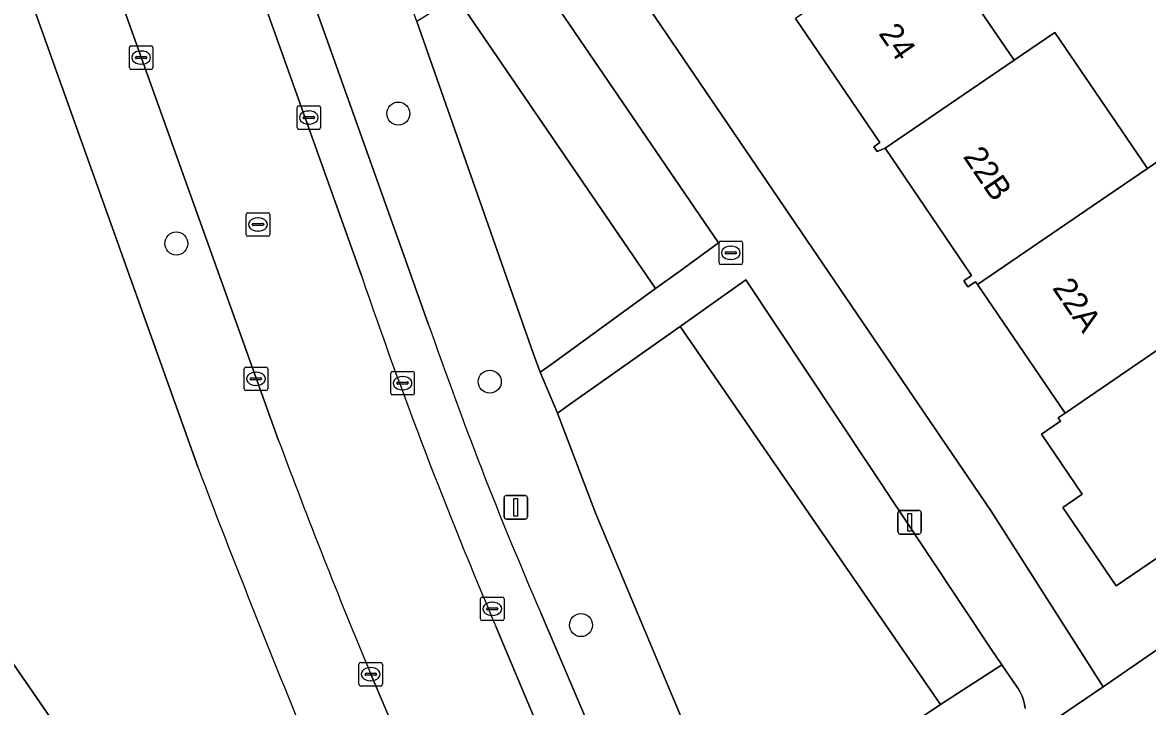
# Model space of a CAD drawing. Extents: x 157445 to 158888, y 383061 to 384688.
# Drawn here: x 158006.18 to 158053.95, y 383391.87 to 383420.9 of the extents above; entities that cross this region are included whole.
import ezdxf

# ---------------------------------------------------------------- set-up
doc = ezdxf.new("R2010")
doc.units = 0
for name, color, linetype in [('IMGEO_Boom', 7, 'Continuous'), ('IMGEO_Erf', 7, 'Continuous'), ('IMGEO_Groenvoorziening', 7, 'Continuous'), ('IMGEO_Kolk', 7, 'Continuous'), ('IMGEO_Lichtmast', 7, 'Continuous'), ('IMGEO_Pand', 7, 'Continuous'), ('IMGEO_Pand_nummerreeks', 7, 'Continuous'), ('IMGEO_Parkeervlak_open', 7, 'Continuous'), ('IMGEO_Rijbaan_lokaal_gesloten', 7, 'Continuous'), ('IMGEO_Rioolput', 7, 'Continuous'), ('IMGEO_Voetpad_open', 7, 'Continuous')]:
    doc.layers.add(name, color=color, linetype=linetype)

msp = doc.modelspace()

# ---------------------------------------------------------------- linework, layer by layer
at = {"layer": 'IMGEO_Boom'}
for centre in [(158022.135, 383417.035), (158012.708, 383411.521), (158026.019, 383405.658), (158029.891, 383395.328)]:
    msp.add_circle(centre, 0.489, dxfattribs=at)
at = {"layer": 'IMGEO_Erf'}
for points in [[(158056.615, 383429.6), (158053.223, 383434.593), (158051.051, 383433.111), (158049.016, 383436.093), (158046.866, 383439.244), (158049.038, 383440.726), (158045.945, 383445.259), (158044.482, 383444.292), (158039.206, 383440.804), (158028.037, 383433.42), (158028.2, 383433.181), (158025.942, 383431.583), (158047.304, 383400.16), (158052.068, 383392.71), (158058.3, 383397.002)], [(158013.62, 383402.046), (158004.962, 383426.227), (158004.459, 383427.633), (158000.558, 383426.024)], [(158044.512, 383424.838), (158048.284, 383419.3), (158050.011, 383420.476), (158053.943, 383414.702), (158055.521, 383415.778)], [(158056.504, 383399.639), (158052.618, 383396.993), (158050.349, 383400.324), (158051.176, 383400.887), (158049.442, 383403.432), (158050.252, 383403.984), (158050.154, 383404.128), (158050.445, 383404.327), (158046.73, 383409.781), (158046.649, 383409.9), (158046.322, 383409.677), (158046.142, 383409.941), (158046.477, 383410.169), (158042.804, 383415.561), (158042.471, 383415.422), (158042.33, 383415.629), (158042.586, 383415.803), (158038.995, 383421.074)]]:
    msp.add_lwpolyline(points, dxfattribs=at)
msp.add_lwpolyline([(157981.4, 383406.529), (157984.101, 383408.396), (157991.898, 383413.783), (158000, 383402.05), (158014.654, 383380.83), (158014.224, 383380.534), (158006.84, 383375.45), (158002.435, 383372.417), (158000, 383375.946), (157993.757, 383384.994), (157990.787, 383389.287), (157990.398, 383389.849), (157983.821, 383399.385), (157981.515, 383402.715), (157983.246, 383403.901)], close=True, dxfattribs=at)
msp.add_arc((158391.121, 383545.013), 403.666, 200.74263, 202.81798, dxfattribs=at)
at = {"layer": 'IMGEO_Groenvoorziening'}
for points in [[(158027.4, 383423.773), (158024.62, 383421.967), (158033.06, 383409.607), (158034.083, 383410.348), (158035.735, 383411.543)], [(158022.919, 383420.946), (158027.86, 383406.874), (158028.157, 383406.056), (158028.619, 383406.39), (158033.06, 383409.607), (158024.62, 383421.967), (158023.399, 383421.234)], [(158036.898, 383409.977), (158034.101, 383407.999), (158045.156, 383391.955), (158047.758, 383393.647), (158047.302, 383394.311)], [(158034.101, 383407.999), (158029.41, 383404.684), (158028.89, 383404.32), (158030.52, 383400.045), (158034.143, 383391.42), (158035.809, 383387.677), (158036.432, 383386.518), (158036.596, 383386.232), (158045.156, 383391.955)]]:
    msp.add_lwpolyline(points, close=True, dxfattribs=at)
msp.add_lwpolyline([(158048.757, 383391.791), (158048.727, 383391.969), (158048.681, 383392.145), (158048.619, 383392.316), (158048.542, 383392.48), (158048.451, 383392.637), (158048.417, 383392.688), (158047.758, 383393.647), (158045.156, 383391.955), (158036.596, 383386.232), (158036.774, 383385.921), (158037.176, 383385.22)], dxfattribs=at)
at = {"layer": 'IMGEO_Kolk'}
for p, q in [((158010.715, 383418.984), (158010.715, 383419.836)), ((158010.79, 383419.91), (158011.642, 383419.91)), ((158011.203, 383419.69), (158011.228, 383419.69)), ((158011.716, 383419.836), (158011.716, 383418.984)), ((158010.974, 383419.404), (158010.974, 383419.416)), ((158011.412, 383419.367), (158011.014, 383419.367)), ((158011.017, 383419.453), (158011.415, 383419.453)), ((158011.226, 383419.13), (158011.201, 383419.13)), ((158011.458, 383419.416), (158011.458, 383419.404)), ((158011.642, 383418.91), (158010.79, 383418.91)), ((158017.835, 383416.439), (158017.835, 383417.291)), ((158017.91, 383417.365), (158018.762, 383417.365)), ((158018.323, 383417.145), (158018.348, 383417.145)), ((158018.836, 383417.291), (158018.836, 383416.439)), ((158018.094, 383416.859), (158018.094, 383416.871)), ((158018.532, 383416.822), (158018.134, 383416.822)), ((158018.137, 383416.908), (158018.535, 383416.908)), ((158018.578, 383416.871), (158018.578, 383416.859)), ((158018.762, 383416.365), (158017.91, 383416.365)), ((158018.346, 383416.585), (158018.321, 383416.585)), ((158035.754, 383410.698), (158035.754, 383411.55)), ((158035.829, 383411.624), (158036.681, 383411.624)), ((158036.242, 383411.404), (158036.267, 383411.404)), ((158036.755, 383411.55), (158036.755, 383410.698)), ((158036.013, 383411.118), (158036.013, 383411.13)), ((158036.451, 383411.081), (158036.053, 383411.081)), ((158036.056, 383411.167), (158036.454, 383411.167)), ((158036.497, 383411.13), (158036.497, 383411.118)), ((158036.681, 383410.624), (158035.829, 383410.624)), ((158036.265, 383410.844), (158036.24, 383410.844)), ((158015.589, 383405.351), (158015.589, 383406.203)), ((158015.664, 383406.277), (158016.516, 383406.277)), ((158016.59, 383406.203), (158016.59, 383405.351)), ((158015.848, 383405.771), (158015.848, 383405.783)), ((158016.286, 383405.734), (158015.888, 383405.734)), ((158015.891, 383405.82), (158016.289, 383405.82)), ((158016.077, 383406.057), (158016.102, 383406.057)), ((158016.332, 383405.783), (158016.332, 383405.771)), ((158021.814, 383405.17), (158021.814, 383406.022)), ((158021.889, 383406.096), (158022.741, 383406.096)), ((158022.302, 383405.876), (158022.327, 383405.876)), ((158022.815, 383406.022), (158022.815, 383405.17)), ((158016.516, 383405.277), (158015.664, 383405.277)), ((158016.1, 383405.497), (158016.075, 383405.497)), ((158022.073, 383405.59), (158022.073, 383405.602)), ((158022.511, 383405.553), (158022.113, 383405.553)), ((158022.116, 383405.639), (158022.514, 383405.639)), ((158022.325, 383405.316), (158022.3, 383405.316)), ((158022.557, 383405.602), (158022.557, 383405.59)), ((158022.741, 383405.096), (158021.889, 383405.096)), ((158025.623, 383395.59), (158025.623, 383396.442)), ((158025.698, 383396.516), (158026.55, 383396.516)), ((158026.111, 383396.296), (158026.136, 383396.296)), ((158026.624, 383396.442), (158026.624, 383395.59)), ((158025.882, 383396.01), (158025.882, 383396.022)), ((158026.32, 383395.973), (158025.922, 383395.973)), ((158025.925, 383396.059), (158026.323, 383396.059)), ((158026.134, 383395.736), (158026.109, 383395.736)), ((158026.366, 383396.022), (158026.366, 383396.01)), ((158026.55, 383395.516), (158025.698, 383395.516)), ((158020.538, 383393.741), (158021.39, 383393.741)), ((158020.463, 383392.815), (158020.463, 383393.667)), ((158020.722, 383393.235), (158020.722, 383393.247)), ((158020.765, 383393.284), (158021.163, 383393.284)), ((158020.951, 383393.521), (158020.976, 383393.521)), ((158021.206, 383393.247), (158021.206, 383393.235)), ((158021.464, 383393.667), (158021.464, 383392.815)), ((158021.16, 383393.198), (158020.762, 383393.198)), ((158020.974, 383392.961), (158020.949, 383392.961)), ((158021.39, 383392.741), (158020.538, 383392.741))]:
    msp.add_line(p, q, dxfattribs=at)
for points in [[(158010.715, 383418.984), (158010.715, 383419.836)], [(158010.79, 383419.91), (158011.642, 383419.91)], [(158011.716, 383419.836), (158011.716, 383418.984)], [(158011.642, 383418.91), (158010.79, 383418.91)], [(158017.835, 383416.439), (158017.835, 383417.291)], [(158017.91, 383417.365), (158018.762, 383417.365)], [(158018.836, 383417.291), (158018.836, 383416.439)], [(158018.762, 383416.365), (158017.91, 383416.365)], [(158035.754, 383410.698), (158035.754, 383411.55)], [(158035.829, 383411.624), (158036.681, 383411.624)], [(158036.755, 383411.55), (158036.755, 383410.698)], [(158036.681, 383410.624), (158035.829, 383410.624)], [(158015.589, 383405.351), (158015.589, 383406.203)], [(158015.664, 383406.277), (158016.516, 383406.277)], [(158016.59, 383406.203), (158016.59, 383405.351)], [(158021.814, 383405.17), (158021.814, 383406.022)], [(158021.889, 383406.096), (158022.741, 383406.096)], [(158022.815, 383406.022), (158022.815, 383405.17)], [(158016.516, 383405.277), (158015.664, 383405.277)], [(158022.741, 383405.096), (158021.889, 383405.096)], [(158025.623, 383395.59), (158025.623, 383396.442)], [(158025.698, 383396.516), (158026.55, 383396.516)], [(158026.624, 383396.442), (158026.624, 383395.59)], [(158026.55, 383395.516), (158025.698, 383395.516)], [(158020.538, 383393.741), (158021.39, 383393.741)], [(158020.463, 383392.815), (158020.463, 383393.667)], [(158021.464, 383393.667), (158021.464, 383392.815)], [(158021.39, 383392.741), (158020.538, 383392.741)]]:
    msp.add_lwpolyline(points, dxfattribs=at)
for centre, radius, start, end in [((158010.792, 383419.834), 0.0765, 91.552, 178.448), ((158010.792, 383419.834), 0.0765, 91.552, 178.448), ((158011.64, 383419.834), 0.0765, 1.552, 88.448), ((158011.64, 383419.834), 0.0765, 1.552, 88.448), ((158011.014, 383419.413), 0.0403, 85.8775, 175.7526), ((158011.011, 383419.403), 0.0366, 178.938, 274.7102), ((158011.415, 383419.41), 0.043, 264.8664, 352.4533), ((158011.419, 383419.415), 0.0386, 1.7309, 96.639), ((158010.792, 383418.986), 0.0765, 181.552, 268.448), ((158010.792, 383418.986), 0.0765, 181.552, 268.448), ((158011.64, 383418.986), 0.0765, 271.552, 358.448), ((158011.64, 383418.986), 0.0765, 271.552, 358.448), ((158017.912, 383417.289), 0.0765, 91.552, 178.448), ((158017.912, 383417.289), 0.0765, 91.552, 178.448), ((158018.76, 383417.289), 0.0765, 1.552, 88.448), ((158018.76, 383417.289), 0.0765, 1.552, 88.448), ((158018.134, 383416.868), 0.0403, 85.8775, 175.7526), ((158018.131, 383416.858), 0.0366, 178.938, 274.7102), ((158018.535, 383416.865), 0.043, 264.8664, 352.4533), ((158018.539, 383416.87), 0.0386, 1.7309, 96.639), ((158017.912, 383416.441), 0.0765, 181.552, 268.448), ((158017.912, 383416.441), 0.0765, 181.552, 268.448), ((158018.76, 383416.441), 0.0765, 271.552, 358.448), ((158018.76, 383416.441), 0.0765, 271.552, 358.448), ((158035.831, 383411.548), 0.0765, 91.552, 178.448), ((158035.831, 383411.548), 0.0765, 91.552, 178.448), ((158036.679, 383411.548), 0.0765, 1.552, 88.448), ((158036.679, 383411.548), 0.0765, 1.552, 88.448), ((158036.053, 383411.127), 0.0403, 85.8775, 175.7526), ((158036.05, 383411.117), 0.0366, 178.938, 274.7102), ((158036.454, 383411.124), 0.043, 264.8664, 352.4533), ((158036.458, 383411.129), 0.0386, 1.7309, 96.639), ((158035.831, 383410.7), 0.0765, 181.552, 268.448), ((158035.831, 383410.7), 0.0765, 181.552, 268.448), ((158036.679, 383410.7), 0.0765, 271.552, 358.448), ((158036.679, 383410.7), 0.0765, 271.552, 358.448), ((158015.666, 383406.201), 0.0765, 91.552, 178.448), ((158015.666, 383406.201), 0.0765, 91.552, 178.448), ((158016.514, 383406.201), 0.0765, 1.552, 88.448), ((158016.514, 383406.201), 0.0765, 1.552, 88.448), ((158015.888, 383405.78), 0.0403, 85.8775, 175.7526), ((158015.885, 383405.77), 0.0366, 178.938, 274.7102), ((158016.289, 383405.777), 0.043, 264.8664, 352.4533), ((158016.293, 383405.782), 0.0386, 1.7309, 96.639), ((158021.891, 383406.02), 0.0765, 91.552, 178.448), ((158021.891, 383406.02), 0.0765, 91.552, 178.448), ((158022.739, 383406.02), 0.0765, 1.552, 88.448), ((158022.739, 383406.02), 0.0765, 1.552, 88.448), ((158015.666, 383405.353), 0.0765, 181.552, 268.448), ((158015.666, 383405.353), 0.0765, 181.552, 268.448), ((158016.514, 383405.353), 0.0765, 271.552, 358.448), ((158016.514, 383405.353), 0.0765, 271.552, 358.448), ((158022.113, 383405.599), 0.0403, 85.8775, 175.7526), ((158022.11, 383405.589), 0.0366, 178.938, 274.7102), ((158022.514, 383405.596), 0.043, 264.8664, 352.4533), ((158022.518, 383405.601), 0.0386, 1.7309, 96.639), ((158021.891, 383405.172), 0.0765, 181.552, 268.448), ((158021.891, 383405.172), 0.0765, 181.552, 268.448), ((158022.739, 383405.172), 0.0765, 271.552, 358.448), ((158022.739, 383405.172), 0.0765, 271.552, 358.448), ((158025.7, 383396.44), 0.0765, 91.552, 178.448), ((158025.7, 383396.44), 0.0765, 91.552, 178.448), ((158026.548, 383396.44), 0.0765, 1.552, 88.448), ((158026.548, 383396.44), 0.0765, 1.552, 88.448), ((158025.922, 383396.019), 0.0403, 85.8775, 175.7526), ((158025.919, 383396.009), 0.0366, 178.938, 274.7102), ((158026.323, 383396.016), 0.043, 264.8664, 352.4533), ((158026.327, 383396.021), 0.0386, 1.7309, 96.639), ((158025.7, 383395.592), 0.0765, 181.552, 268.448), ((158025.7, 383395.592), 0.0765, 181.552, 268.448), ((158026.548, 383395.592), 0.0765, 271.552, 358.448), ((158026.548, 383395.592), 0.0765, 271.552, 358.448), ((158020.54, 383393.665), 0.0765, 91.552, 178.448), ((158020.54, 383393.665), 0.0765, 91.552, 178.448), ((158021.388, 383393.665), 0.0765, 1.552, 88.448), ((158021.388, 383393.665), 0.0765, 1.552, 88.448), ((158020.762, 383393.244), 0.0403, 85.8775, 175.7526), ((158020.759, 383393.234), 0.0366, 178.938, 274.7102), ((158021.163, 383393.241), 0.043, 264.8664, 352.4533), ((158021.167, 383393.246), 0.0386, 1.7309, 96.639), ((158020.54, 383392.817), 0.0765, 181.552, 268.448), ((158020.54, 383392.817), 0.0765, 181.552, 268.448), ((158021.388, 383392.817), 0.0765, 271.552, 358.448), ((158021.388, 383392.817), 0.0765, 271.552, 358.448)]:
    msp.add_arc(centre, radius, start, end, dxfattribs=at)
for centre, major_axis, ratio, start_param, end_param in [((158011.202, 383419.41), (-0.387, 0.002), 0.722429, 4.712389, 7.853982), ((158011.227, 383419.41), (-0.39, 0.002), 0.717154, 1.570796, 4.712389), ((158018.322, 383416.865), (-0.387, 0.002), 0.722429, 4.712389, 7.853982), ((158018.347, 383416.865), (-0.39, 0.002), 0.717154, 1.570796, 4.712389), ((158036.241, 383411.124), (-0.387, 0.002), 0.722429, 4.712389, 7.853982), ((158036.266, 383411.124), (-0.39, 0.002), 0.717154, 1.570796, 4.712389), ((158016.076, 383405.777), (-0.387, 0.002), 0.722429, 4.712389, 7.853982), ((158016.101, 383405.777), (-0.39, 0.002), 0.717154, 1.570796, 4.712389), ((158022.301, 383405.596), (-0.387, 0.002), 0.722429, 4.712389, 7.853982), ((158022.326, 383405.596), (-0.39, 0.002), 0.717154, 1.570796, 4.712389), ((158026.11, 383396.016), (-0.387, 0.002), 0.722429, 4.712389, 7.853982), ((158026.135, 383396.016), (-0.39, 0.002), 0.717154, 1.570796, 4.712389), ((158020.95, 383393.241), (-0.387, 0.002), 0.722429, 4.712389, 7.853982), ((158020.975, 383393.241), (-0.39, 0.002), 0.717154, 1.570796, 4.712389)]:
    msp.add_ellipse(centre, major_axis=major_axis, ratio=ratio, start_param=start_param, end_param=end_param, dxfattribs=at)
at = {"layer": 'IMGEO_Lichtmast'}
for p, q in [((158026.627, 383399.927), (158026.627, 383400.727)), ((158026.627, 383400.727), (158026.627, 383399.927)), ((158026.727, 383400.827), (158027.517, 383400.827)), ((158027.517, 383400.827), (158026.727, 383400.827)), ((158027.617, 383400.727), (158027.617, 383399.927)), ((158027.617, 383399.927), (158027.617, 383400.727)), ((158043.349, 383399.293), (158043.349, 383400.093)), ((158043.349, 383400.093), (158043.349, 383399.293)), ((158043.449, 383400.193), (158044.239, 383400.193)), ((158044.239, 383400.193), (158043.449, 383400.193)), ((158044.339, 383400.093), (158044.339, 383399.293)), ((158044.339, 383399.293), (158044.339, 383400.093)), ((158027.517, 383399.827), (158026.727, 383399.827)), ((158026.727, 383399.827), (158027.517, 383399.827)), ((158044.239, 383399.193), (158043.449, 383399.193)), ((158043.449, 383399.193), (158044.239, 383399.193))]:
    msp.add_line(p, q, dxfattribs=at)
for points in [[(158027.047, 383400.702), (158027.197, 383400.702), (158027.197, 383399.952), (158027.047, 383399.952), (158027.047, 383400.702)], [(158043.769, 383400.068), (158043.919, 383400.068), (158043.919, 383399.318), (158043.769, 383399.318), (158043.769, 383400.068)]]:
    msp.add_lwpolyline(points, dxfattribs=at)
for centre, start, end in [((158026.727, 383400.727), 90, 180), ((158026.727, 383400.727), 90, 180), ((158027.517, 383400.727), 0, 90), ((158027.517, 383400.727), 360, 90), ((158026.727, 383399.927), 180, 270), ((158026.727, 383399.927), 180, 270), ((158027.517, 383399.927), 270, 0), ((158027.517, 383399.927), 270, 0), ((158043.449, 383400.093), 90, 180), ((158043.449, 383400.093), 90, 180), ((158044.239, 383400.093), 0, 90), ((158044.239, 383400.093), 360, 90), ((158043.449, 383399.293), 180, 270), ((158043.449, 383399.293), 180, 270), ((158044.239, 383399.293), 270, 0), ((158044.239, 383399.293), 270, 0)]:
    msp.add_arc(centre, 0.1, start, end, dxfattribs=at)
at = {"layer": 'IMGEO_Pand'}
for points in [[(158044.512, 383424.838), (158038.995, 383421.074), (158042.586, 383415.803), (158042.33, 383415.629), (158042.471, 383415.422), (158042.804, 383415.561), (158048.284, 383419.3)], [(158053.943, 383414.702), (158050.011, 383420.476), (158048.284, 383419.3), (158042.804, 383415.561), (158046.477, 383410.169), (158046.142, 383409.941), (158046.322, 383409.677), (158046.649, 383409.9), (158046.73, 383409.781), (158052.217, 383413.524)], [(158059.236, 383410.324), (158055.521, 383415.778), (158053.943, 383414.702), (158052.217, 383413.524), (158046.73, 383409.781), (158050.445, 383404.327), (158055.932, 383408.07)], [(157981.4, 383406.529), (157983.246, 383403.901), (157981.515, 383402.715), (157983.821, 383399.385), (157990.398, 383389.849), (157990.787, 383389.287), (157993.757, 383384.994), (158000, 383375.946), (158002.435, 383372.417), (158006.84, 383375.45), (158014.224, 383380.534), (158014.654, 383380.83), (158000, 383402.05), (157991.898, 383413.783), (157984.101, 383408.396)], [(158055.932, 383408.07), (158050.445, 383404.327), (158050.154, 383404.128), (158050.252, 383403.984), (158049.442, 383403.432), (158051.176, 383400.887), (158050.349, 383400.324), (158052.618, 383396.993), (158056.504, 383399.639), (158058.3, 383397.002), (158063.482, 383400.533), (158061.467, 383403.493), (158059.814, 383402.368)]]:
    msp.add_lwpolyline(points, close=True, dxfattribs=at)
at = {"layer": 'IMGEO_Parkeervlak_open'}
for points in [[(158023.408, 383408.118), (158022.449, 383410.792), (158017.713, 383424.083), (158015.846, 383423.401), (158020.582, 383410.118)], [(158030.47, 383390.497), (158028.184, 383395.848)], [(158026.29, 383395.236), (158029.097, 383388.581), (158029.856, 383386.809)]]:
    msp.add_lwpolyline(points, dxfattribs=at)
for centre, radius, start, end in [((158228.325, 383481.262), 219.587, 198.90444, 203.06426), ((158188.044, 383465.137), 174.23, 199.10261, 203.43355)]:
    msp.add_arc(centre, radius, start, end, dxfattribs=at)
at = {"layer": 'IMGEO_Rijbaan_lokaal_gesloten'}
for points in [[(158008.462, 383427.146), (158017.053, 383403.162)], [(158020.582, 383410.118), (158015.846, 383423.401)], [(158029.097, 383388.581), (158026.29, 383395.236)], [(158020.964, 383393.241), (158023.958, 383386.211)]]:
    msp.add_lwpolyline(points, dxfattribs=at)
for centre, radius, start, end in [((158228.325, 383481.262), 219.587, 198.90444, 203.06426), ((158278.421, 383500.466), 278.893, 200.41959, 202.61055)]:
    msp.add_arc(centre, radius, start, end, dxfattribs=at)
at = {"layer": 'IMGEO_Rioolput'}
for p, q in [((158015.751, 383412.829), (158016.603, 383412.829)), ((158015.676, 383411.903), (158015.676, 383412.755)), ((158015.978, 383412.372), (158016.376, 383412.372)), ((158016.164, 383412.609), (158016.189, 383412.609)), ((158016.677, 383412.755), (158016.677, 383411.903)), ((158015.935, 383412.323), (158015.935, 383412.335)), ((158016.373, 383412.286), (158015.975, 383412.286)), ((158016.187, 383412.049), (158016.162, 383412.049)), ((158016.419, 383412.335), (158016.419, 383412.323)), ((158016.603, 383411.829), (158015.751, 383411.829))]:
    msp.add_line(p, q, dxfattribs=at)
for points in [[(158015.751, 383412.829), (158016.603, 383412.829)], [(158015.676, 383411.903), (158015.676, 383412.755)], [(158016.677, 383412.755), (158016.677, 383411.903)], [(158016.603, 383411.829), (158015.751, 383411.829)]]:
    msp.add_lwpolyline(points, dxfattribs=at)
for centre, radius, start, end in [((158015.753, 383412.753), 0.0765, 91.552, 178.448), ((158015.753, 383412.753), 0.0765, 91.552, 178.448), ((158016.601, 383412.753), 0.0765, 1.552, 88.448), ((158016.601, 383412.753), 0.0765, 1.552, 88.448), ((158015.975, 383412.332), 0.0403, 85.8775, 175.7526), ((158016.38, 383412.334), 0.0386, 1.7309, 96.639), ((158015.753, 383411.905), 0.0765, 181.552, 268.448), ((158015.753, 383411.905), 0.0765, 181.552, 268.448), ((158015.972, 383412.322), 0.0366, 178.938, 274.7102), ((158016.376, 383412.329), 0.043, 264.8664, 352.4533), ((158016.601, 383411.905), 0.0765, 271.552, 358.448), ((158016.601, 383411.905), 0.0765, 271.552, 358.448)]:
    msp.add_arc(centre, radius, start, end, dxfattribs=at)
for centre, major_axis, ratio, start_param, end_param in [((158016.163, 383412.329), (-0.387, 0.002), 0.722429, 4.712389, 7.853982), ((158016.188, 383412.329), (-0.39, 0.002), 0.717154, 1.570796, 4.712389)]:
    msp.add_ellipse(centre, major_axis=major_axis, ratio=ratio, start_param=start_param, end_param=end_param, dxfattribs=at)
at = {"layer": 'IMGEO_Voetpad_open'}
for points in [[(158028.89, 383404.32), (158028.157, 383406.056), (158027.86, 383406.874), (158022.919, 383420.946), (158021.294, 383425.422), (158021.218, 383425.636), (158019.047, 383431.614), (158019.012, 383431.727), (158013.895, 383446.185)], [(157998.224, 383445.465), (157998.111, 383445.386), (157998.261, 383444.967), (158002.475, 383433.184), (158004.459, 383427.633), (158004.962, 383426.227), (158013.62, 383402.046)], [(158017.053, 383403.162), (158008.462, 383427.146), (158007.453, 383426.807), (158004.08, 383436.242), (158005.086, 383436.671), (158004.525, 383438.354), (158002.912, 383442.704)], [(158011.237, 383442.394), (158015.654, 383429.815), (158016.741, 383430.198), (158018.771, 383424.392), (158017.713, 383424.083), (158022.449, 383410.792), (158023.408, 383408.118)], [(158047.924, 383389.889), (158052.068, 383392.71), (158047.304, 383400.16), (158025.942, 383431.583)], [(158027.4, 383423.773), (158035.735, 383411.543), (158034.083, 383410.348), (158033.06, 383409.607), (158028.619, 383406.39), (158028.157, 383406.056), (158028.89, 383404.32), (158029.41, 383404.684), (158034.101, 383407.999), (158036.898, 383409.977), (158047.302, 383394.311), (158047.758, 383393.647), (158048.417, 383392.688), (158048.451, 383392.637), (158048.542, 383392.48), (158048.619, 383392.316), (158048.681, 383392.145), (158048.727, 383391.969), (158048.757, 383391.791)], [(158092.695, 383420.508), (158091.439, 383419.648), (158073.391, 383407.283), (158072.236, 383406.492), (158068.434, 383403.904), (158063.482, 383400.533), (158058.3, 383397.002), (158052.068, 383392.71), (158047.924, 383389.889), (158042.562, 383386.072), (158040.072, 383384.455)], [(158031.45, 383384.681), (158032.058, 383384.164), (158032.975, 383383.378), (158033.554, 383382.657), (158034.281, 383381.706), (158034.641, 383381.039), (158035.546, 383381.71), (158041.231, 383373.486), (158041.794, 383377.569), (158040.67, 383379.315), (158039.822, 383380.755), (158037.249, 383385.065), (158037.176, 383385.22), (158036.774, 383385.921), (158036.596, 383386.232), (158036.432, 383386.518), (158035.809, 383387.677), (158034.143, 383391.42), (158030.52, 383400.045), (158028.89, 383404.32)], [(158028.184, 383395.848), (158030.47, 383390.497)], [(158023.958, 383386.211), (158020.964, 383393.241)]]:
    msp.add_lwpolyline(points, dxfattribs=at)
for centre, radius, start, end in [((158188.044, 383465.137), 174.23, 199.10261, 203.43355), ((158278.421, 383500.466), 278.893, 200.41959, 202.61055), ((158391.121, 383545.013), 403.666, 200.74263, 202.81798)]:
    msp.add_arc(centre, radius, start, end, dxfattribs=at)

# ---------------------------------------------------------------- texts
at = {"layer": 'IMGEO_Pand_nummerreeks'}
for s, rotation, p in [('24', 304.6386, (158042.502, 383420.43)), ('22B', 304.1882, (158046.089, 383415.209)), ('22A', 304.2569, (158049.879, 383409.634))]:
    msp.add_text(s, height=1, rotation=rotation, dxfattribs=at).set_placement(p)

doc.saveas('drawing.dxf')
